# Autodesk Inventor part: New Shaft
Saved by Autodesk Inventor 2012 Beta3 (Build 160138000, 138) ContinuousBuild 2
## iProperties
Created: 2011-01
Part Number: New Shaft
Material: Steel
Document SubType Name: Modeling
Designer: Beta-8540w
Density: 1 g/cm^3
CustomPartVersion: 1
Author: Beta-8540w
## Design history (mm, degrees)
sketch "Main Sketch"
  geometry: L1 (0, 0)-(51, 0) reference; L2 (0, 0)-(0, 5); L3 (0, 5)-(10, 5); L4 (10, 5)-(10, 6); L5 (10, 6)-(13, 6); L6 (13, 6)-(13, 12.5); L7 (25, 12.5)-(25, 6); L8 (13, 12.5)-(25, 12.5); L9 (41, 6)-(41, 5); L10 (25, 6)-(41, 6); L11 (51, 5)-(51, 0); L12 (41, 5)-(51, 5)
  constraints: 24 end point, 7 horizontal, 6 vertical
  dimensions: "d3" = 10 diameter of L3 L1 (derived); "d4" = 12 diameter of L5 L1 (derived); "d5" = 25 diameter of L8 L1 (derived); "d6" = 12 diameter of L10 L1 (derived); "d7" = 10 diameter of L12 L1 (derived)
revolve "Revolution1" sketch "Main Sketch" stored, may be unused: angle "d8" = 0 deg
chamfer "Chamfer1" distance "d9" = 0.3; stored, may be unused: second distance "d10" = 0.125, angle "d11" = 45 deg
chamfer "Chamfer2" distance "d12" = 0.3; stored, may be unused: second distance "d13" = 0.125, angle "d14" = 45 deg
node "Spur Gear Teeth2"
body "Solid1"
feature "Spur Gear Feature 1"
other parameters: "d0" = 0, "d1" = 0, "d2" = 0
